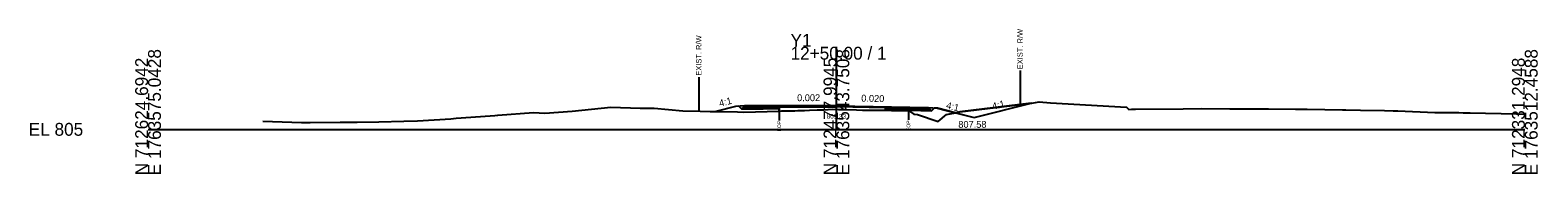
# Model space of a CAD drawing. Extents: x -26 to 1303, y -10 to 9524.
# Drawn here: x -25.7 to 302.8, y 2490.3 to 2521.6 of the extents above; entities that cross this region are included whole.
import ezdxf

# ---------------------------------------------------------------- set-up
doc = ezdxf.new("R2010")
doc.units = 0
for name, color, linetype in [('Default', 7, 'Continuous'), ('Exist CMT Pavement', 7, 'Continuous'), ('Exist Cross Section Cell', 7, 'Continuous'), ('Exist XS Center Line Elevation Label', 7, 'Continuous'), ('Exist XS Ground Line', 7, 'Continuous'), ('Old_Level_10', 7, 'Continuous'), ('Prop CMT Pvmt Course 1', 7, 'Continuous'), ('Prop CMT Pvmt Course 3', 7, 'Continuous'), ('Prop CMT Pvmt Surface', 7, 'Continuous'), ('Prop CMT Pvmt Surface Shoulder', 7, 'Continuous'), ('Prop CMT Shld Paved Course 1', 7, 'Continuous'), ('Prop CMT Shld Paved Course 3', 7, 'Continuous'), ('Prop CMT Slope Grass', 7, 'Continuous'), ('Prop CMT Subgrade Earthwork', 7, 'Continuous'), ('Prop XS Ditch Standard Text', 7, 'Continuous'), ('Prop XS Earthwork Shape', 7, 'Continuous'), ('Prop XS SE Text', 7, 'Continuous'), ('Prop XS Side Slope Text', 7, 'Continuous'), ('Prop XS Wedging', 7, 'Continuous')]:
    doc.layers.add(name, color=color, linetype=linetype)

msp = doc.modelspace()

# ---------------------------------------------------------------- linework, layer by layer
at = {"layer": 'Exist CMT Pavement'}
msp.add_lwpolyline([(137.51, 2503.99), (138, 2504), (139, 2504.01), (140.94, 2504.06), (141.56, 2504.09), (143.04, 2504.13), (144.11, 2504.15), (145.77, 2504.22), (146.67, 2504.25), (147.26, 2504.27), (149.22, 2504.36), (150.46, 2504.32), (151.47, 2504.3), (151.78, 2504.3), (152.27, 2504.29), (154.34, 2504.25), (155.68, 2504.21), (156.9, 2504.18), (157.79, 2504.18), (159.64, 2504.19), (160.24, 2504.21), (160.72, 2504.2)], dxfattribs=at)
at = {"layer": 'Exist Cross Section Cell'}
for p, q in [((150, 2500), (150, 2517.98)), ((0, 2500), (150, 2500)), ((150, 2500), (300, 2500))]:
    msp.add_line(p, q, dxfattribs=at)
at = {"layer": 'Exist XS Ground Line'}
msp.add_lwpolyline([(25.02, 2501.77), (33.41, 2501.52), (35.3, 2501.5), (41.84, 2501.53), (45.53, 2501.57), (50.26, 2501.6), (55.76, 2501.75), (58.69, 2501.88), (65.98, 2502.31), (67.12, 2502.42), (72.46, 2502.81), (75.55, 2502.99), (76.21, 2503.09), (83.98, 2503.67), (86.43, 2503.55), (92.41, 2503.94), (96.66, 2504.39), (100.84, 2504.86), (107.2, 2504.58), (110.25, 2504.61), (116.53, 2504.06), (120.34, 2503.97), (122.52, 2503.92), (124.99, 2503.92), (128.45, 2503.81), (129.76, 2503.77), (137.51, 2503.99), (138, 2504), (139, 2504.01), (140.94, 2504.06), (141.56, 2504.09), (143.04, 2504.13), (144.11, 2504.15), (145.77, 2504.22), (146.67, 2504.25), (147.26, 2504.27), (149.22, 2504.36), (150.46, 2504.32), (151.47, 2504.3), (151.78, 2504.3), (152.27, 2504.29), (154.34, 2504.25), (155.68, 2504.21), (156.9, 2504.18), (157.79, 2504.18), (159.64, 2504.19), (160.24, 2504.21), (160.72, 2504.2), (161.29, 2504.16), (162.01, 2504.12), (164.11, 2504.1), (164.45, 2504.09), (165.12, 2504.08), (165.69, 2504.09), (166.88, 2503.31), (167.66, 2503.25), (172.17, 2501.74), (174, 2503.21), (176.9, 2503.78), (192.55, 2505.7), (194.15, 2505.99), (196.66, 2505.8), (213.19, 2504.84), (213.69, 2504.34), (214.26, 2504.37), (215.19, 2504.41), (225.53, 2504.47), (229.6, 2504.51), (235.69, 2504.47), (239.83, 2504.43), (244.12, 2504.44), (250.06, 2504.38), (252.55, 2504.36), (260.28, 2504.28), (260.98, 2504.27), (264.23, 2504.21), (269.4, 2504.11), (271.29, 2504.03), (271.76, 2504.01), (272.34, 2504), (280.4, 2503.69), (285.65, 2503.67), (286.55, 2503.57), (287.26, 2503.57), (288.08, 2503.57), (298.21, 2503.38), (300, 2503.29)], dxfattribs=at)
at = {"layer": 'Old_Level_10'}
for p, q in [((120, 2511.38), (120, 2503.97)), ((190, 2512.79), (190, 2505.39)), ((137.51, 2503.99), (137.51, 2501.94)), ((165.69, 2504.09), (165.69, 2502.04))]:
    msp.add_line(p, q, dxfattribs=at)
at = {"layer": 'Prop CMT Pvmt Course 1'}
for points in [[(150, 2505.14), (134, 2505.12)], [(134, 2505.12), (134, 2504.87)], [(134, 2504.87), (150, 2504.89)], [(134, 2504.87), (134, 2504.87)], [(134, 2504.87), (134, 2504.87)], [(150, 2504.89), (150, 2505.14)], [(150, 2505.14), (166, 2504.82)], [(150, 2504.89), (150, 2504.89), (150, 2504.89)], [(160.72, 2504.68), (150, 2504.89)], [(166, 2504.57), (160.72, 2504.68)], [(160.72, 2504.68), (160.72, 2504.68)], [(166, 2504.82), (166, 2504.57)]]:
    msp.add_lwpolyline(points, dxfattribs=at)
at = {"layer": 'Prop CMT Pvmt Course 3'}
for points in [[(134, 2504.87), (134, 2504.45)], [(137.51, 2504.87), (137.51, 2504.46)], [(160.72, 2504.68), (166, 2504.57)], [(160.72, 2504.26), (160.72, 2504.68)], [(166, 2504.16), (160.72, 2504.26)], [(166, 2504.57), (166, 2504.16)]]:
    msp.add_lwpolyline(points, dxfattribs=at)
at = {"layer": 'Prop CMT Pvmt Surface'}
for points in [[(150, 2505.14), (134, 2505.12)], [(150, 2505.14), (166, 2504.82)]]:
    msp.add_lwpolyline(points, dxfattribs=at)
at = {"layer": 'Prop CMT Pvmt Surface Shoulder'}
for points in [[(134, 2505.12), (130, 2505.11)], [(166, 2504.82), (170, 2504.74)]]:
    msp.add_lwpolyline(points, dxfattribs=at)
at = {"layer": 'Prop CMT Shld Paved Course 1'}
for points in [[(134, 2505.12), (130, 2505.11), (129.75, 2504.86)], [(129.75, 2504.86), (134, 2504.87)], [(134, 2504.87), (134, 2505.12)], [(166, 2504.82), (170, 2504.74), (170.26, 2504.49)], [(166, 2504.57), (166, 2504.82)], [(170.26, 2504.49), (166, 2504.57)]]:
    msp.add_lwpolyline(points, dxfattribs=at)
at = {"layer": 'Prop CMT Shld Paved Course 3'}
for points in [[(129.75, 2504.86), (129.33, 2504.44)], [(129.33, 2504.44), (134, 2504.45)], [(134, 2504.87), (129.75, 2504.86)], [(134, 2504.53), (134, 2504.87)], [(166, 2504.57), (170.26, 2504.49)], [(166, 2504.24), (166, 2504.57)], [(170.68, 2504.06), (166, 2504.16)], [(170.26, 2504.49), (170.68, 2504.06)]]:
    msp.add_lwpolyline(points, dxfattribs=at)
at = {"layer": 'Prop CMT Slope Grass'}
for points in [[(130, 2505.11), (128, 2504.99), (123.73, 2503.92)], [(170, 2504.74), (172, 2504.58), (180, 2502.58), (192.42, 2505.69)], [(170, 2504.74), (172, 2504.58), (175.65, 2503.67)]]:
    msp.add_lwpolyline(points, dxfattribs=at)
at = {"layer": 'Prop CMT Subgrade Earthwork'}
for p, q in [((134, 2504.45), (129.33, 2504.44)), ((137.51, 2504.46), (134, 2504.45)), ((137.51, 2504.46), (137.51, 2503.99)), ((160.72, 2504.2), (160.72, 2504.26)), ((160.72, 2504.26), (166, 2504.16)), ((165.99, 2504.16), (170.68, 2504.06))]:
    msp.add_line(p, q, dxfattribs=at)
for points in [[(128.74, 2505.03), (129.33, 2504.44)], [(171.26, 2504.64), (170.68, 2504.06)]]:
    msp.add_lwpolyline(points, dxfattribs=at)
at = {"layer": 'Prop XS Earthwork Shape'}
for points in [[(137.51, 2504.46), (134, 2504.45), (129.33, 2504.44), (128.74, 2505.03), (128, 2504.99), (123.73, 2503.92), (124.99, 2503.92), (128.45, 2503.81), (129.76, 2503.77), (137.51, 2503.99)], [(160.72, 2504.2), (161.29, 2504.16), (162.01, 2504.12), (164.11, 2504.1), (164.45, 2504.09), (165.12, 2504.08), (165.69, 2504.09), (166.88, 2503.31), (167.66, 2503.25), (172.17, 2501.74), (174, 2503.21), (175.96, 2503.59), (175.65, 2503.67), (172, 2504.58), (171.26, 2504.64), (170.68, 2504.06), (166, 2504.16), (165.99, 2504.16), (160.72, 2504.26)], [(175.96, 2503.59), (180, 2502.58), (192.42, 2505.69), (176.9, 2503.78)]]:
    msp.add_lwpolyline(points, close=True, dxfattribs=at)
at = {"layer": 'Prop XS Wedging'}
for p, q in [((137.51, 2503.99), (138, 2504)), ((138, 2504), (139, 2504.01)), ((141.56, 2504.09), (143.04, 2504.13)), ((145.77, 2504.22), (146.67, 2504.25)), ((148.12, 2504.31), (149.22, 2504.36)), ((149.22, 2504.36), (150.46, 2504.32)), ((150.46, 2504.32), (151.47, 2504.3)), ((151.47, 2504.3), (151.78, 2504.3)), ((151.78, 2504.3), (152.27, 2504.29)), ((152.27, 2504.29), (154.34, 2504.25)), ((154.34, 2504.25), (155.68, 2504.21)), ((160.72, 2504.2), (160.72, 2504.35))]:
    msp.add_line(p, q, dxfattribs=at)
for points in [[(160.72, 2504.35), (160.72, 2504.68), (150, 2504.89), (137.51, 2504.87), (137.51, 2504.54)], [(137.51, 2504.54), (137.51, 2504.21), (137.51, 2503.99)], [(139, 2504.01), (140.94, 2504.06), (141.56, 2504.09)], [(143.04, 2504.13), (144.11, 2504.15), (145.77, 2504.22)], [(146.67, 2504.25), (147.26, 2504.27), (148.12, 2504.31)], [(155.68, 2504.21), (156.9, 2504.18), (157.79, 2504.18), (159.64, 2504.19)], [(159.64, 2504.19), (160.24, 2504.21), (160.72, 2504.2)]]:
    msp.add_lwpolyline(points, dxfattribs=at)

# ---------------------------------------------------------------- texts
at = {"layer": 'Default'}
msp.add_text('-', height=0.0001, dxfattribs=at).set_placement((0, 2500))
at = {"layer": 'Exist Cross Section Cell'}
for s, p in [('Y1', (140, 2517.98)), ('12+50.00 / 1', (140, 2515.18)), ('EL 805', (-26, 2498.6))]:
    msp.add_text(s, height=2.8, dxfattribs=at).set_placement(p)
for s, p in [('E 1763575.0428', (2.8, 2490)), ('E 1763543.7508', (152.8, 2490)), ('E 1763512.4588', (302.8, 2490)), ('N 712624.6942', (0, 2490)), ('N 712477.9945', (150, 2490)), ('N 712331.2948', (300, 2490))]:
    msp.add_text(s, height=2.8, rotation=90, dxfattribs=at).set_placement(p)
at = {"layer": 'Exist XS Center Line Elevation Label'}
msp.add_text('809.33', height=1, dxfattribs=at).set_placement((147.88, 2502.33))
at = {"layer": 'Old_Level_10'}
for s, height, p in [('EXIST. R/W', 1.181, (120.59, 2511.68)), ('EXIST. R/W', 1.181, (190.59, 2513.09)), ('EOP', 0.787, (137.91, 2499.54)), ('EOP', 0.787, (166.09, 2499.64))]:
    msp.add_text(s, height=height, rotation=90, dxfattribs=at).set_placement(p)
at = {"layer": 'Prop XS Ditch Standard Text'}
msp.add_text('807.58', height=1.5, dxfattribs=at).set_placement((176.56, 2500.33))
at = {"layer": 'Prop XS SE Text'}
for s, rotation, p in [('0.002', 0.0958, (141.43, 2506.13)), ('0.020', 358.8542, (155.4, 2506.04))]:
    msp.add_text(s, height=1.5, rotation=rotation, dxfattribs=at).set_placement(p)
at = {"layer": 'Prop XS Side Slope Text'}
for rotation, p in [(14.0362, (124.62, 2504.91)), (345.9638, (173.8, 2504.57)), (14.0363, (184.12, 2504.25))]:
    msp.add_text('4:1', height=1.5, rotation=rotation, dxfattribs=at).set_placement(p)

doc.saveas('drawing.dxf')
